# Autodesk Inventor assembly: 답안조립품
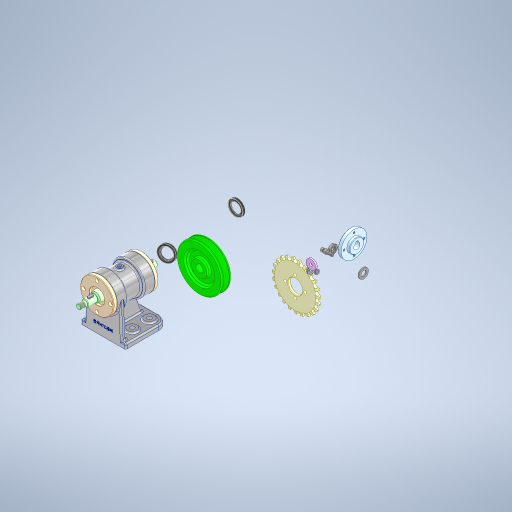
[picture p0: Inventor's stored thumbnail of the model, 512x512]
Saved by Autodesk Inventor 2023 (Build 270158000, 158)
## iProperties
Created: 2024-02
Part Number: 답안조립품
Document SubType Name: Assembly
Designer: home
Author: home
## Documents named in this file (18)
- C:\Users\home\Desktop\740204V1006\답안조립품.iam
- C:\Users\home\Desktop\740204V1006\본체.ipt
- C:\Users\home\Desktop\740204V1006\V-벨트풀리.ipt
- C:\Users\home\Desktop\740204V1006\가스켓.ipt
- C:\Users\home\Desktop\740204V1006\깊은 홈 볼 베어링 6204.ipt
- C:\Users\home\Desktop\740204V1006\스프로킷.ipt
- C:\Users\home\Desktop\740204V1006\스프링 와셔 M5.ipt
- C:\Users\home\Desktop\740204V1006\스프링 와셔 M10.ipt
- C:\Users\home\Desktop\740204V1006\앤드 캡.ipt
- C:\Users\home\Desktop\740204V1006\오일 실 20 32 5.ipt
- C:\Users\home\Desktop\740204V1006\육각 너트 M10x1.ipt
- C:\Users\home\Desktop\740204V1006\육각 소켓 머리 볼트 M4 x 10.ipt
- C:\Users\home\Desktop\740204V1006\육각 소켓 머리 볼트 M5 x 12.ipt
- C:\Users\home\Desktop\740204V1006\축.ipt
- C:\Users\home\Desktop\740204V1006\커버.ipt
- C:\Users\home\Desktop\740204V1006\평와셔 M10.ipt
- C:\Users\home\Desktop\740204V1006\평행 키 5x5x12.ipt
- C:\Users\home\Desktop\740204V1006\플랜지.ipt
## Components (4 placed, 3 different names)
1. V-벨트풀리:1
2. 가스켓:1
3. 플랜지:1
4. 가스켓:2
